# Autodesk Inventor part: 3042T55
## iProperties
Shininess: 64.0
Length Units: 11272
Angle Units: 11279
Time Units: 11290
Mass Units: 11286
Length Display Precision: 3
Angle Display Precision: 2
Compacted: True
Part Number: 3042T55
Document SubType Name: Modeling
Created: 2003-10
Designer: bhowe
Manufacturer: Standard
Standards Organization: Custom
Material: Stainless Steel, Type 304
Description: U-BOLT, 4 IN, Stainless Steel, Austenitic
Density: 0.0
Volumn: 0.0
Area: 0.0
PropertySet Name: Model Information
Control State: 0
Master: False
Checked Out: False
Author: bhowe
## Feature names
1. U-Bolt Sweep1
2. Guillotine Extrusion1 [Extrusion]
3. Insert Extrusion2 [Extrusion]
4. Washer Extrusion3 [Extrusion]
5. Hex Nut Extrusion4 [Extrusion]
6. Chamfer1
